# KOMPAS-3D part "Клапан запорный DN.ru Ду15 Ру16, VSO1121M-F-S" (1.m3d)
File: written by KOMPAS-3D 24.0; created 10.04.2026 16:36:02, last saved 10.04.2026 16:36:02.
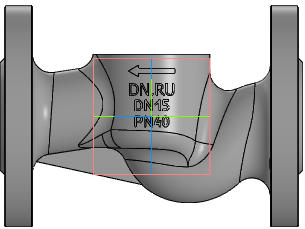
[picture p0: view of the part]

Document properties: Автор: R2D2; Полное имя файла: E:\Работа\Зайцев\VSO3131M-F-S Клапан запорный DN.ru Ду15-100 Ру40\DN15\исходные материалы\1.m3d

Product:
- Component [assembly]: Сборка  | qty 1  | pos. 1  | Масса: 4.342816; Автор: R2D2; source file: dn15_3d_step.a3d
- Body: Тело 1  | qty 1
    Масса: 0.715787
- Component [standard]: Фланец 15-1-01-1-B-ВЧ40-I-dв 19 ГОСТ 33259-2015  | qty 1  | Раздел спецификации: Стандартные изделия; additional columns: BOSimple***Material:38d6725a-5efe-48e1-b177-a7817acb862a
- Part/product: Клапан запорный DN.ru Ду15 Ру16  | designation VSO1121M-F-S
    Масса: 3.1
    Раздел спецификации: Прочие изделия
    Примечание: D090-01942

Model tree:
1. Эскиз:1
2. Элемент выдавливания:1  (labels: Грань.Твердое тело1)
     Расстояние 1 = 25.9987; Смещение 1 = 1
3. Эскиз:2  (with: Ребро.Элемент выдавливания:1)
4. Элемент выдавливания:2
     Расстояние 1 = 500
5. Эскиз:3
6. Элемент выдавливания:3  (with: Грань.Элемент выдавливания:1)  (labels: Грань.Твердое тело1; Твердое тело1; Solid1)
     Расстояние 1 = 500; Расстояние = 40

Referenced files in E:\Работа\Зайцев\VSO3131M-F-S Клапан запорный DN.ru Ду15-100 Ру40\DN15\исходные материалы\: dn15_3d_step.a3d
Referenced files in C:\Program Files\ASCON\KOMPAS-3D v24\Libs\PolynomLib\DATA\vault\Methods\Kompas\3D\: PLib_Flange_GOST_33259_1401.m3d
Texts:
  BOSimple***Material:38d6725a-5efe-48e1-b177-a7817acb862a
  BOSimple***PART:3f5f0d7e-d4da-47dc-6145-6a7f26b7079a***SHORTLOC:B6A6_23E38AE8DB154823[I;1;Круглый;15;1;19;0;ВЧ40 ГОСТ 7293-85]
  VSO1121M-F-S
  DN15
  GOST 26.020 Pr3
  PN40
  ВЧ40 ГОСТ 7293-85
  Ch34
  Ось Z.Начало координат
  Ось Y.Начало координат
  Плоскость ZX.Начало координат
  Plane ZX. Origin
  Плоскость ZY.Начало координат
